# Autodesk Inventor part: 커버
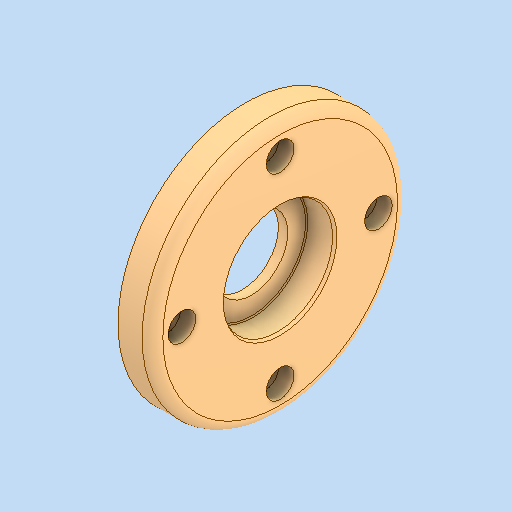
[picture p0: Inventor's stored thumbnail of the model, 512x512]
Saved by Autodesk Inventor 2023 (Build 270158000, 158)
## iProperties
Created: 2024-11
Part Number: 커버
Material: 알루미늄 6061
Document SubType Name: Modeling
Designer: asung
Density: 2.7 g/cm^3
Appearance: 기본값
Author: jhkim
Sending System: Autodesk Inventor 2025
Preprocessor: ST-DEVELOPER v20
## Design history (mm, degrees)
node "커버1"
node "솔리드2"
node "솔리드1"
